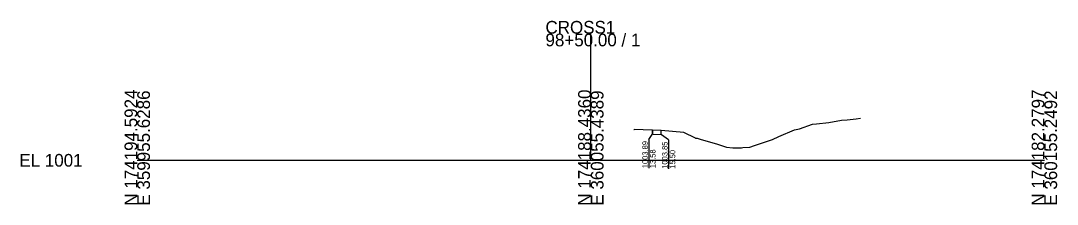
# Model space of a CAD drawing. Extents: x -26 to 1403, y -10 to 11027.
# Drawn here: x 1174.3 to 1402.8, y 1990.3 to 2030.8 of the extents above; entities that cross this region are included whole.
import ezdxf

# ---------------------------------------------------------------- set-up
doc = ezdxf.new("R2010")
doc.units = 0
for name, color, linetype in [('Default', 7, 'Continuous'), ('P_E_XS_Ground', 7, 'Continuous'), ('P_XS_EAR_CommonGrnd', 7, 'Continuous'), ('P_XS_Lane', 7, 'Continuous'), ('P_XS_Rock', 7, 'Continuous')]:
    doc.layers.add(name, color=color, linetype=linetype)

msp = doc.modelspace()

# ---------------------------------------------------------------- linework, layer by layer
at = {"layer": 'Default'}
for p, q in [((1300, 2000), (1300, 2027.93)), ((1200, 2000), (1300, 2000)), ((1300, 2000), (1400, 2000))]:
    msp.add_line(p, q, dxfattribs=at)
at = {"layer": 'P_E_XS_Ground'}
for p, q in [((1352.5, 2008.36), (1355.24, 2008.88)), ((1355.24, 2008.88), (1356.51, 2008.96)), ((1356.51, 2008.96), (1358.53, 2009.15)), ((1358.53, 2009.15), (1359.45, 2009.31)), ((1309.48, 2006.79), (1309.58, 2006.78)), ((1315.5, 2006.54), (1309.58, 2006.78)), ((1320.5, 2006.14), (1315.5, 2006.54)), ((1341.47, 2005.26), (1344.9, 2006.71)), ((1344.9, 2006.71), (1345.98, 2006.95)), ((1345.98, 2006.95), (1348.85, 2007.97)), ((1348.85, 2007.97), (1349.73, 2008.03)), ((1349.73, 2008.03), (1352.5, 2008.36)), ((1323.05, 2004.86), (1320.5, 2006.14)), ((1323.05, 2004.86), (1323.43, 2004.91)), ((1323.43, 2004.91), (1324.32, 2004.57)), ((1324.32, 2004.57), (1327.7, 2003.6)), ((1336.08, 2003.29), (1340.03, 2004.62)), ((1340.03, 2004.62), (1341.47, 2005.26)), ((1327.7, 2003.6), (1329.88, 2002.88)), ((1329.88, 2002.88), (1331.34, 2002.72)), ((1331.34, 2002.72), (1332.34, 2002.73)), ((1332.34, 2002.73), (1333.23, 2002.73)), ((1333.23, 2002.73), (1333.55, 2002.85)), ((1333.55, 2002.85), (1335.04, 2002.92)), ((1335.04, 2002.92), (1336.08, 2003.29))]:
    msp.add_line(p, q, dxfattribs=at)
at = {"layer": 'P_XS_EAR_CommonGrnd'}
msp.add_lwpolyline([(1315.5, 2005.71), (1315.5, 2006.54), (1313.58, 2006.62), (1313.58, 2005.78)], close=True, dxfattribs=at)
at = {"layer": 'P_XS_Lane'}
for p, q in [((1313.58, 2005.78), (1313.58, 2006.62)), ((1315.5, 2005.71), (1315.5, 2006.54)), ((1313.58, 2005.78), (1315.5, 2005.71))]:
    msp.add_line(p, q, dxfattribs=at)
at = {"layer": 'P_XS_Rock'}
for p, q in [((1312.81, 2004.61), (1313.51, 2005.69)), ((1312.81, 2004.61), (1312.81, 1998.26)), ((1317.16, 2004.49), (1315.57, 2005.61)), ((1317.16, 2004.49), (1317.16, 1998.14))]:
    msp.add_line(p, q, dxfattribs=at)

# ---------------------------------------------------------------- texts
at = {"layer": 'Default'}
for s, p in [('CROSS1', (1290, 2027.93)), ('98+50.00 / 1', (1290, 2025.13)), ('EL 1001', (1174, 1998.6))]:
    msp.add_text(s, height=2.8, dxfattribs=at).set_placement(p)
for s, p in [('N 174194.5924', (1200, 1990)), ('E 359955.6286', (1202.8, 1990)), ('N 174188.4360', (1300, 1990)), ('E 360055.4389', (1302.8, 1990)), ('N 174182.2797', (1400, 1990)), ('E 360155.2492', (1402.8, 1990))]:
    msp.add_text(s, height=2.8, rotation=90, dxfattribs=at).set_placement(p)
at = {"layer": 'P_XS_Rock'}
for s, p in [('1003.89', (1312.56, 1998.26)), ('13.58', (1314.26, 1998.26)), ('1003.85', (1316.91, 1998.14)), ('15.50', (1318.61, 1998.14))]:
    msp.add_text(s, height=1.2, rotation=90, dxfattribs=at).set_placement(p)

doc.saveas('drawing.dxf')
